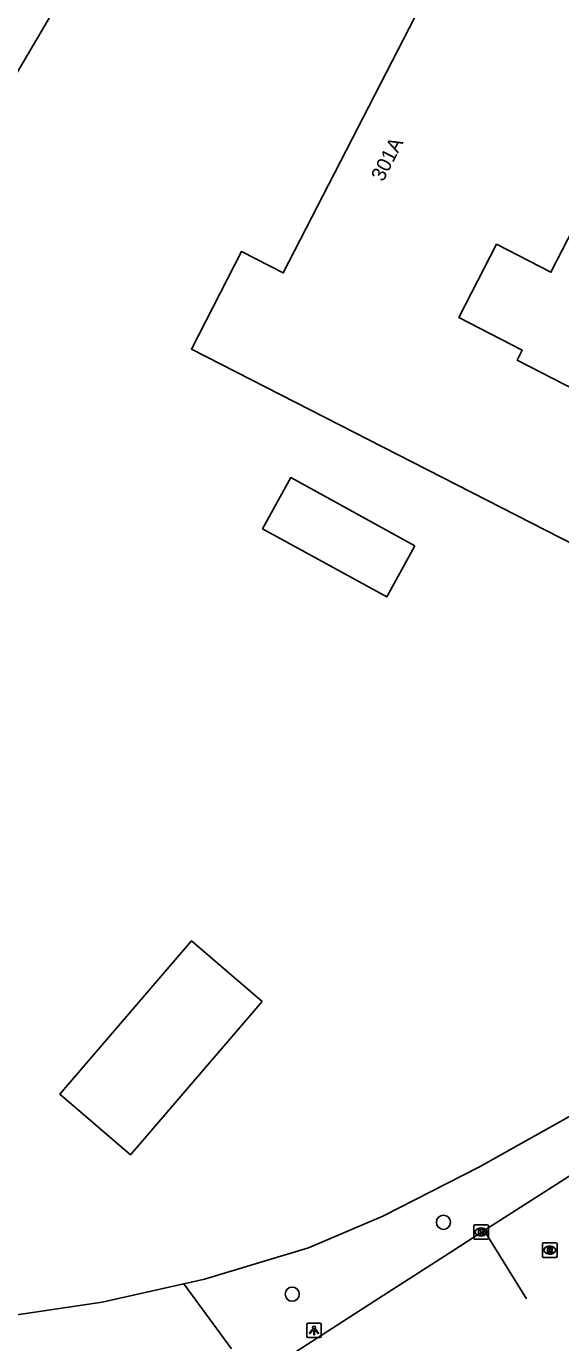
# Model space of a CAD drawing. Extents: x 160158 to 160921, y 381517 to 382041.
# Drawn here: x 160262.6 to 160299.5, y 381630.6 to 381721.4 of the extents above; entities that cross this region are included whole.
import ezdxf

# ---------------------------------------------------------------- set-up
doc = ezdxf.new("R2010")
doc.units = 0
for name, color, linetype in [('IMGEO_Boom', 7, 'Continuous'), ('IMGEO_Kolk', 7, 'Continuous'), ('IMGEO_Lichtpunt', 7, 'Continuous'), ('IMGEO_Muur', 7, 'Continuous'), ('IMGEO_Pand', 7, 'Continuous'), ('IMGEO_Pand_nummerreeks', 7, 'Continuous'), ('IMGEO_Parkeervlak_open', 7, 'Continuous'), ('IMGEO_Rijbaan_lokaal_gesloten', 7, 'Continuous'), ('IMGEO_Rijbaan_lokaal_open', 7, 'Continuous'), ('IMGEO_Rioolput', 7, 'Continuous'), ('IMGEO_Voetpad_open', 7, 'Continuous')]:
    doc.layers.add(name, color=color, linetype=linetype)

msp = doc.modelspace()

# ---------------------------------------------------------------- linework, layer by layer
at = {"layer": 'IMGEO_Boom'}
for centre in [(160291.387, 381638.886), (160280.954, 381633.925)]:
    msp.add_circle(centre, 0.489, dxfattribs=at)
at = {"layer": 'IMGEO_Kolk'}
for p, q in [((160293.486, 381637.787), (160293.486, 381638.639)), ((160293.561, 381638.713), (160294.413, 381638.713)), ((160293.974, 381638.493), (160293.999, 381638.493)), ((160294.487, 381638.639), (160294.487, 381637.787)), ((160294.413, 381637.713), (160293.561, 381637.713)), ((160293.997, 381637.933), (160293.972, 381637.933))]:
    msp.add_line(p, q, dxfattribs=at)
for points in [[(160293.486, 381637.787), (160293.486, 381638.639)], [(160293.561, 381638.713), (160294.413, 381638.713)], [(160293.807, 381638.413), (160293.93, 381638.413), (160293.93, 381638.262), (160294.06, 381638.413), (160294.224, 381638.413), (160294.078, 381638.262), (160294.231, 381638.013), (160294.079, 381638.013), (160293.994, 381638.177), (160293.93, 381638.11), (160293.93, 381638.013), (160293.807, 381638.013), (160293.807, 381638.413)], [(160294.487, 381638.639), (160294.487, 381637.787)], [(160294.413, 381637.713), (160293.561, 381637.713)]]:
    msp.add_lwpolyline(points, dxfattribs=at)
for centre, start, end in [((160293.563, 381638.637), 91.55205, 178.44795), ((160293.563, 381638.637), 91.55205, 178.44795), ((160294.411, 381638.637), 1.55205, 88.44795), ((160294.411, 381638.637), 1.55205, 88.44795), ((160293.563, 381637.789), 181.55205, 268.44795), ((160293.563, 381637.789), 181.55205, 268.44795), ((160294.411, 381637.789), 271.55205, 358.44795), ((160294.411, 381637.789), 271.55205, 358.44795)]:
    msp.add_arc(centre, 0.0765, start, end, dxfattribs=at)
for centre, major_axis, ratio, start_param, end_param in [((160293.973, 381638.213), (-0.387, 0.002), 0.722429, 4.712389, 7.853982), ((160293.998, 381638.213), (-0.39, 0.002), 0.717154, 1.570796, 4.712389)]:
    msp.add_ellipse(centre, major_axis=major_axis, ratio=ratio, start_param=start_param, end_param=end_param, dxfattribs=at)
at = {"layer": 'IMGEO_Lichtpunt'}
for p, q in [((160281.96, 381631.828), (160281.96, 381631.021)), ((160281.96, 381631.828), (160281.96, 381631.021)), ((160282.862, 381631.923), (160282.054, 381631.923)), ((160282.862, 381631.923), (160282.054, 381631.923)), ((160282.956, 381631.021), (160282.956, 381631.828)), ((160282.956, 381631.021), (160282.956, 381631.828)), ((160282.054, 381630.927), (160282.862, 381630.927)), ((160282.054, 381630.927), (160282.862, 381630.927))]:
    msp.add_line(p, q, dxfattribs=at)
for points in [[(160282.334, 381631.492), (160282.373, 381631.464), (160282.185, 381631.202), (160282.147, 381631.229), (160282.334, 381631.492)], [(160282.436, 381631.444), (160282.483, 381631.444), (160282.483, 381631.122), (160282.436, 381631.122), (160282.436, 381631.444)], [(160282.546, 381631.464), (160282.584, 381631.491), (160282.771, 381631.229), (160282.732, 381631.201), (160282.546, 381631.464)]]:
    msp.add_lwpolyline(points, dxfattribs=at)
msp.add_circle((160282.459, 381631.626), 0.0994, dxfattribs=at)
for centre, start, end in [((160282.054, 381631.828), 90, 180), ((160282.054, 381631.828), 90, 180), ((160282.862, 381631.828), 0, 90), ((160282.862, 381631.828), 0, 90), ((160282.054, 381631.021), 180, 270), ((160282.054, 381631.021), 180, 270), ((160282.862, 381631.021), 270, 0), ((160282.862, 381631.021), 270, 360)]:
    msp.add_arc(centre, 0.0946, start, end, dxfattribs=at)
at = {"layer": 'IMGEO_Muur'}
msp.add_lwpolyline([(160303.442, 381648.074), (160293.877, 381642.708), (160287.207, 381639.31), (160282.085, 381637.13), (160274.895, 381634.961), (160267.832, 381633.38), (160260.673, 381632.321)], dxfattribs=at)
at = {"layer": 'IMGEO_Pand'}
for points in [[(160307.608, 381681.94), (160273.993, 381699.123), (160277.451, 381705.859), (160280.332, 381704.379), (160290.186, 381723.569)], [(160264.508, 381722.515), (160261.97, 381718.208), (160260.488, 381715.692), (160258.076, 381717.114), (160255.727, 381712.974), (160252.671, 381714.765)], [(160306.254, 381694.228), (160305.063, 381694.84), (160304.703, 381694.138), (160296.476, 381698.363), (160296.83, 381699.051), (160292.452, 381701.299), (160295.05, 381706.358), (160298.809, 381704.428), (160303.907, 381714.356), (160312.795, 381709.793), (160312.418, 381709.057), (160313.565, 381708.468), (160306.254, 381694.228)], [(160289.414, 381685.552), (160287.474, 381682.024), (160278.913, 381686.73), (160280.853, 381690.259), (160289.414, 381685.552)], [(160278.874, 381654.109), (160274.008, 381658.297), (160264.915, 381647.73), (160269.782, 381643.543), (160278.874, 381654.109)]]:
    msp.add_lwpolyline(points, dxfattribs=at)
at = {"layer": 'IMGEO_Parkeervlak_open'}
msp.add_lwpolyline([(160273.476, 381634.643), (160267.832, 381633.38), (160260.673, 381632.321), (160254.538, 381631.736), (160246.171, 381631.2)], dxfattribs=at)
at = {"layer": 'IMGEO_Rijbaan_lokaal_gesloten'}
msp.add_lwpolyline([(160294.195, 381638.32), (160292.105, 381636.955), (160286.577, 381633.43), (160280.872, 381629.729)], dxfattribs=at)
at = {"layer": 'IMGEO_Rijbaan_lokaal_open'}
for points in [[(160313.889, 381650.901), (160294.195, 381638.32)], [(160294.195, 381638.32), (160297.121, 381633.596)]]:
    msp.add_lwpolyline(points, dxfattribs=at)
at = {"layer": 'IMGEO_Rioolput'}
for p, q in [((160298.225, 381636.54), (160298.225, 381637.392)), ((160298.3, 381637.466), (160299.152, 381637.466)), ((160298.713, 381637.246), (160298.738, 381637.246)), ((160299.226, 381637.392), (160299.226, 381636.54)), ((160299.152, 381636.466), (160298.3, 381636.466)), ((160298.736, 381636.686), (160298.711, 381636.686))]:
    msp.add_line(p, q, dxfattribs=at)
for points in [[(160298.225, 381636.54), (160298.225, 381637.392)], [(160298.3, 381637.466), (160299.152, 381637.466)], [(160299.226, 381637.392), (160299.226, 381636.54)], [(160299.152, 381636.466), (160298.3, 381636.466)], [(160298.814, 381637.164), (160298.562, 381637.166), (160298.562, 381636.766)], [(160298.562, 381636.766), (160298.686, 381636.766), (160298.686, 381636.928), (160298.697, 381636.928)], [(160298.74, 381637.085), (160298.686, 381637.085), (160298.686, 381637.004)], [(160298.686, 381637.004), (160298.738, 381637.004)], [(160298.744, 381636.899), (160298.815, 381636.766), (160298.955, 381636.766), (160298.89, 381636.892)]]:
    msp.add_lwpolyline(points, dxfattribs=at)
for centre, radius, start, end in [((160298.302, 381637.39), 0.0765, 91.55205, 178.44795), ((160298.302, 381637.39), 0.0765, 91.55205, 178.44795), ((160299.15, 381637.39), 0.0765, 1.55205, 88.44795), ((160299.15, 381637.39), 0.0765, 1.55205, 88.44795), ((160298.302, 381636.542), 0.0765, 181.55205, 268.44795), ((160298.302, 381636.542), 0.0765, 181.55205, 268.44795), ((160298.696, 381636.875), 0.0533, 26.02933, 88.69889), ((160298.722, 381637.193), 0.19, 274.7715, 282.96867), ((160298.746, 381636.989), 0.0964, 77.00612, 93.18647), ((160298.76, 381637.046), 0.0378, 276.66336, 79.67722), ((160298.813, 381637.054), 0.109, 350.36119, 89.41601), ((160298.811, 381637.054), 0.112, 277.58423, 350.98172), ((160298.795, 381636.839), 0.108, 29.51342, 73.79051), ((160299.15, 381636.542), 0.0765, 271.55205, 358.44795), ((160299.15, 381636.542), 0.0765, 271.55205, 358.44795)]:
    msp.add_arc(centre, radius, start, end, dxfattribs=at)
for centre, major_axis, ratio, start_param, end_param in [((160298.712, 381636.966), (-0.387, 0.002), 0.722429, 4.712389, 7.853982), ((160298.737, 381636.966), (-0.39, 0.002), 0.717154, 1.570796, 4.712389)]:
    msp.add_ellipse(centre, major_axis=major_axis, ratio=ratio, start_param=start_param, end_param=end_param, dxfattribs=at)
at = {"layer": 'IMGEO_Voetpad_open'}
for points in [[(160369.922, 381690.69), (160360.83, 381685.003), (160360.513, 381685.494), (160355.37, 381682.336), (160355.613, 381681.967), (160335.072, 381668.419), (160315.003, 381655.51), (160303.442, 381648.074), (160293.877, 381642.708), (160287.207, 381639.31), (160282.085, 381637.13), (160274.895, 381634.961), (160273.476, 381634.643)], [(160273.476, 381634.643), (160276.764, 381630.165)]]:
    msp.add_lwpolyline(points, dxfattribs=at)

# ---------------------------------------------------------------- texts
at = {"layer": 'IMGEO_Pand_nummerreeks'}
msp.add_text('301A', height=1, rotation=62.81909, dxfattribs=at).set_placement((160287.226, 381710.622))

doc.saveas('drawing.dxf')
